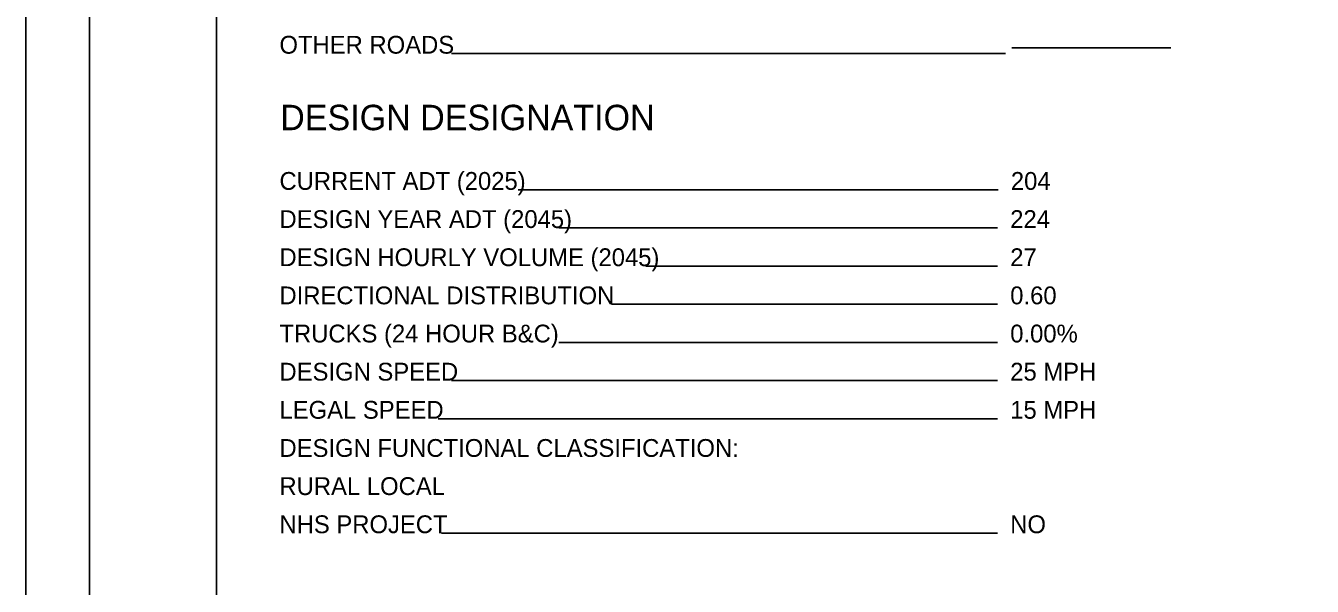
# Model space of a CAD drawing. Extents: x 0 to 81.5, y 0 to 35.2.
# Drawn here: x 0 to 10.11, y 6.69 to 11.1 of the extents above; entities that cross this region are included whole.
import ezdxf

# ---------------------------------------------------------------- set-up
doc = ezdxf.new("R2010")
doc.units = 0
for name, color, linetype in [('SH_Border', 7, 'Continuous'), ('SH_Cut_Line', 7, 'Continuous'), ('SH_Data', 7, 'Continuous'), ('SH_Text', 7, 'Continuous')]:
    doc.layers.add(name, color=color, linetype=linetype)

msp = doc.modelspace()

# ---------------------------------------------------------------- linework, layer by layer
at = {"layer": 'SH_Border'}
for points in [[(0.5, 21.5), (1.5, 21.5), (1.5, 0.5), (0.5, 0.5)], [(1.5, 21.5), (33.5, 21.5), (33.5, 0.5), (1.5, 0.5)]]:
    msp.add_lwpolyline(points, close=True, dxfattribs=at)
at = {"layer": 'SH_Cut_Line'}
msp.add_lwpolyline([(0, 0), (34, 0), (34, 22), (0, 22)], close=True, dxfattribs=at)
at = {"layer": 'SH_Data'}
for p, q in [((9, 10.922), (7.75, 10.922)), ((7.7, 10.877), (3.347, 10.877)), ((7.642, 9.806), (3.871, 9.806)), ((7.637, 9.506), (4.189, 9.506)), ((7.637, 9.206), (4.872, 9.206)), ((7.637, 8.906), (4.604, 8.906)), ((7.637, 8.606), (4.189, 8.606)), ((7.637, 8.306), (3.346, 8.306)), ((7.637, 8.006), (3.242, 8.006)), ((7.637, 7.106), (3.267, 7.106))]:
    msp.add_line(p, q, dxfattribs=at)

# ---------------------------------------------------------------- texts
msp.add_text('DESIGN DESIGNATION', height=0.2, dxfattribs=at).set_placement((2, 10.275))
at = {"layer": 'SH_Text'}
for s, p in [('OTHER ROADS', (1.994, 10.877)), ('CURRENT ADT (2025)', (1.994, 9.806)), ('204   ', (7.742, 9.806)), ('DESIGN YEAR ADT (2045)', (1.994, 9.506)), ('224   ', (7.737, 9.506)), ('DESIGN HOURLY VOLUME (2045)', (1.994, 9.206)), ('27    ', (7.737, 9.206)), ('DIRECTIONAL DISTRIBUTION', (1.994, 8.906)), ('0.60  ', (7.737, 8.906)), ('TRUCKS (24 HOUR B&C)', (1.994, 8.606)), ('0.00% ', (7.737, 8.606)), ('DESIGN SPEED', (1.994, 8.306)), ('25 MPH', (7.737, 8.306)), ('LEGAL SPEED', (1.994, 8.006)), ('15 MPH', (7.737, 8.006)), ('DESIGN FUNCTIONAL CLASSIFICATION:', (1.994, 7.706)), ('RURAL LOCAL                                     ', (1.994, 7.406)), ('NHS PROJECT', (1.994, 7.106)), ('NO    ', (7.737, 7.106))]:
    msp.add_text(s, height=0.14, dxfattribs=at).set_placement(p)

doc.saveas('drawing.dxf')
